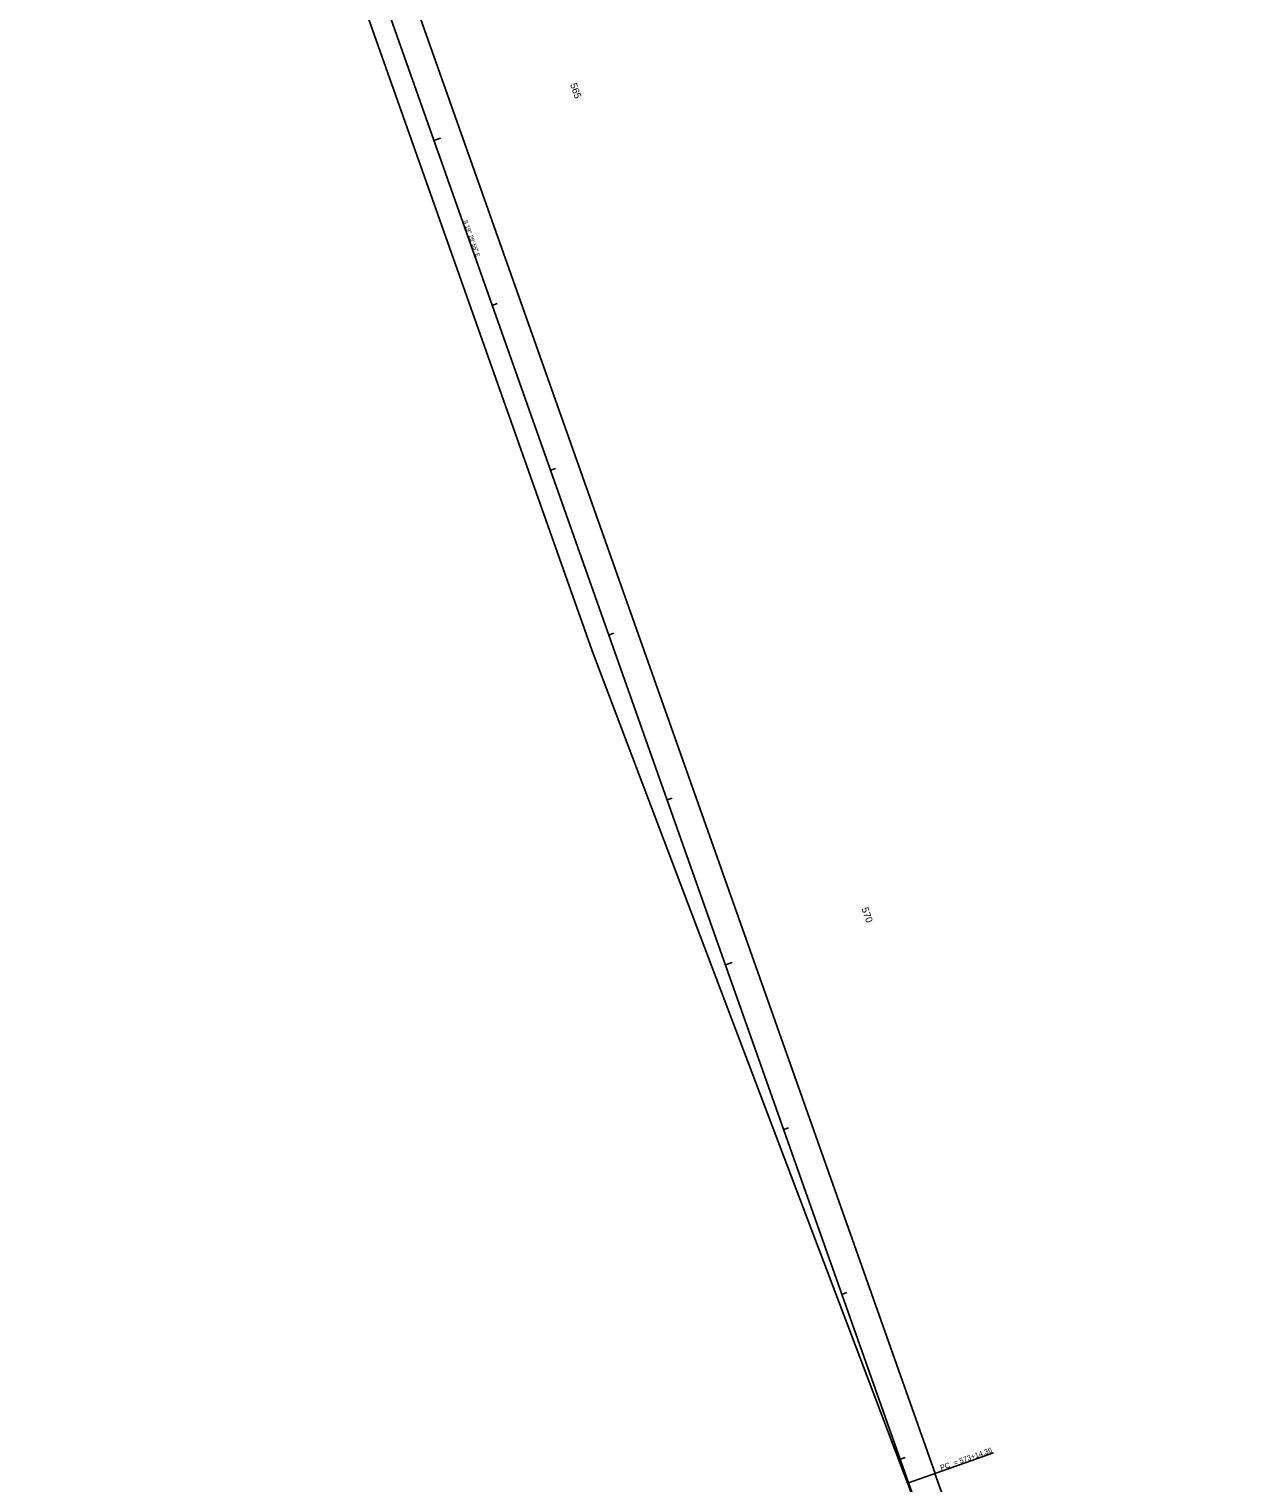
# Model space of a CAD drawing. Extents: x 2005249 to 2006884, y 1134249 to 1137558.
# Drawn here: x 2005747 to 2006448, y 1135896 to 1136727 of the extents above; entities that cross this region are included whole.
import ezdxf

# ---------------------------------------------------------------- set-up
doc = ezdxf.new("R2010")
doc.units = 0
for name, color, linetype in [('RD_DTM_Major1', 7, 'Continuous'), ('RD_DTM_Major1_Lbl', 7, 'Continuous'), ('RD_DTM_Minor1', 7, 'Continuous'), ('RD_DTM_Minor2_Lbl', 7, 'Continuous'), ('RD_Sketch8', 7, 'Continuous')]:
    doc.layers.add(name, color=color, linetype=linetype)

msp = doc.modelspace()

# ---------------------------------------------------------------- linework, layer by layer
at = {"layer": 'RD_DTM_Major1'}
for p, q in [((2005978.73, 1136663.24), (2005982.51, 1136664.58)), ((2006012.09, 1136568.97), (2006014.91, 1136569.97)), ((2006045.44, 1136474.69), (2006048.27, 1136475.69)), ((2006078.79, 1136380.42), (2006081.62, 1136381.42)), ((2006112.14, 1136286.14), (2006114.97, 1136287.14)), ((2006145.49, 1136191.87), (2006149.26, 1136193.2)), ((2006178.84, 1136097.59), (2006181.67, 1136098.59)), ((2006212.19, 1136003.32), (2006215.02, 1136004.32)), ((2006245.54, 1135909.04), (2006248.37, 1135910.05))]:
    msp.add_line(p, q, dxfattribs=at)
at = {"layer": 'RD_DTM_Minor1'}
msp.add_line((2005747.02, 1137318.22), (2006250.33, 1135895.51), dxfattribs=at)
msp.add_arc((2012591.24, 1138138.7), 6726, 199.48201, 203.72857, dxfattribs=at)
at = {"layer": 'RD_DTM_Minor2_Lbl'}
msp.add_line((2006250.33, 1135895.51), (2006298.86, 1135912.67), dxfattribs=at)
at = {"layer": 'RD_Sketch8'}
for p, q in [((2006265.42, 1135900.84), (2005762.11, 1137323.56)), ((2006069.22, 1136371.48), (2005785.74, 1137172.81)), ((2006069.22, 1136371.48), (2006260.7, 1135866.42))]:
    msp.add_line(p, q, dxfattribs=at)
msp.add_arc((2012591.24, 1138138.7), 6710, 199.48201, 203.72857, dxfattribs=at)

# ---------------------------------------------------------------- texts
at = {"layer": 'RD_DTM_Major1_Lbl'}
for s, p in [('565', (2006056.51, 1136695.26)), ('570', (2006223.26, 1136223.9))]:
    msp.add_text(s, height=4, rotation=289.48201, dxfattribs=at).set_placement(p)
at = {"layer": 'RD_DTM_Minor2_Lbl'}
for s, height, rotation, p in [('S 19%%d 28\' 55" E', 2.4, 289.48201, (2005995.52, 1136617.3)), ('PC  = 573+14.36', 3, 19.48201, (2006269.02, 1135902.65))]:
    msp.add_text(s, height=height, rotation=rotation, dxfattribs=at).set_placement(p)

doc.saveas('drawing.dxf')
